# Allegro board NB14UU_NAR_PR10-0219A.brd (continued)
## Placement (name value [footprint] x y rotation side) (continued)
PR27  100K_0402_5%  [R_0402]  89.47 121.79 0 bottom
PR28  100K_0402_5%  [R_0402]  91.24 118.06 0 bottom
PR31  1M_0402_5%  [R_0402]  78.6 122.63 0 top
PR32  1M_0402_5%  [R_0402]  84.13 120.53 0 bottom
PR33  100K_0402_5%  [R_0402]  89.42 118.3 0 bottom
PR38  100_0402_5%  [R_0402]  144.89 41.6 0 top
PR39  100_0402_5%  [R_0402]  144.89 40.84 0 top
PR40  100_0402_5%  [R_0402]  144.89 40.08 0 top
PR41  0_0402_5%  [R0402_0OHM]  83.89 114.56 180 top
PR42  0_0402_5%  [R0402_0OHM]  83.82 115.5 90 top
PR43  0_0402_5%  [R_0402]  82.23 114.56 180 top
PR44  0_0402_5%  [R0402_0OHM]  83.82 118.07 270 top
PR45  10K_0402_5%  [R_0402]  80.58 114.56 180 top
PR46  0_0402_5%  [R0402_0OHM]  86.7 119.83 180 bottom
PR47  0_0402_5%  [R0402_0OHM]  78.67 117.05 270 top
PR49  0_0402_5%  [R0402_0OHM]  88.58 116.85 0 bottom
PR100  0_0603_5%  [R0603_0OHM]  204.72 31.19 270 bottom
PR102  499K_0402_1%  [R_0402]  202.57 38.17 180 bottom
PR103  499K_0402_1%  [R_0402]  202.57 37.35 180 bottom
PR104  0_0402_5%  [R0402_0OHM]  207.45 37.46 90 bottom
PR105  0_0402_5%  [R0402_0OHM]  206.69 37.46 90 bottom
PR106  4.7_1206_5%  [R_1206]  205.61 34.49 180 top
PR107  100K_0402_5%  [R_0402]  200.01 34.81 0 bottom
PR108  1K_0402_5%  [R_0402]  204.34 38.31 270 bottom
PR111  0_0603_5%  [R0603_0OHM]  82.29 73.73 0 bottom
PR112  4.7_1206_5%  [R_1206]  86.8 77.23 90 bottom
PR113  100K_0402_5%  [R_0402]  77.33 69.04 0 bottom
PR114  0_0402_5%  [R_0402]  74.48 69.34 90 bottom
PR116  1M_0402_1%  [R_0402]  75.37 70.64 270 bottom
PR117  1K_0402_5%  [R_0402]  74.48 71.5 90 bottom
PR119  0_0402_5%  [R0402_0OHM]  200.92 35.75 180 bottom
PR120  0_0402_5%  [R0402_0OHM]  200.92 36.51 180 bottom
PR202  4.7_1206_5%  [R_1206]  90.6 63 90 top
PR203  0_0603_5%  [R0603_0OHM]  87.37 63.32 180 bottom
PR204  102K_0402_1%  [R_0402]  87.61 68.72 0 bottom
PR205  0_0402_5%  [R_0402]  87.9 64.17 0 top
PR206  100K_0402_1%  [R_0402]  88.53 66.94 180 bottom
PR207  0_0402_5%  [R_0402]  88.48 65.54 180 top
PR208  0_0402_5%  [R0402_0OHM]  95.89 68.27 180 bottom
PR209  1M_0402_5%  [R_0402]  95.19 69.48 180 bottom
PR210  0_0402_5%  [R0402_0OHM]  96.91 70.43 180 top
PR212  1M_0402_5%  [R_0402]  95.26 70.43 180 top
PR302  1M_0402_1%  [R_0402]  235.28 131.23 0 top
PR303  4.7_1206_5%  [R_1206]  229.17 128.72 180 bottom
PR304  0_0603_5%  [R0603_0OHM]  231.26 127.84 270 top
PR306  22.1K_0402_1%  [R_0402]  231.83 134.64 270 top
PR307  0_0402_5%  [R_0402]  234.31 134.64 270 top
PR308  1K_0402_5%  [R_0402]  232.66 134.64 270 top
PR310  0_0402_5%  [R_0402]  235.14 133.73 90 top
PR311  29.4K_0402_1%  [R_0402]  233.48 133.73 90 top
PR312  22K_0402_1%  [R_0402]  236.19 132.03 180 top
PR313  100K_0402_5%  [R_0402]  236.29 130.34 0 top
PR314  0_0402_5%  [R0402_0OHM]  206.51 111.02 180 bottom
PR315  0_0402_5%  [R0402_0OHM]  204.16 129.49 180 bottom
PR402  0_0402_5%  [R0402_0OHM]  103.87 70.69 0 top
PR403  1M_0402_1%  [R_0402]  104.78 71.57 180 top
PR404  0_0402_5%  [R_0402]  105.6 70.74 90 top
PR405  4.7_0603_5%  [R_0603]  109.15 77.48 90 top
PR406  22K_0402_1%  [R_0402]  211.07 134.83 270 top
PR407  1M_0402_1%  [R_0402]  210.31 133.92 90 top
PR408  0_0402_5%  [R_0402]  213.16 127 90 top
PR409  4.7_0603_5%  [R_0603]  204.21 130.57 0 bottom
PR410  10K_0402_1%  [R_0402]  208.53 134.83 270 top
PR411  0_0402_5%  [R_0402]  210.88 127 90 top
PR412  0_0402_5%  [R_0402]  106.23 78.99 90 top
PR413  10K_0402_1%  [R_0402]  103.56 79.91 270 top
PR414  10K_0402_1%  [R_0402]  102.67 79.91 270 top
PR415  10K_0402_1%  [R_0402]  104.45 78.99 90 top
PR416  10K_0402_1%  [R_0402]  101.79 78.99 90 top
PR417  10K_0402_1%  [R_0402]  211.64 127 90 top
PR418  10K_0402_1%  [R_0402]  214.05 127.91 270 top
PR419  10K_0402_1%  [R_0402]  210.12 127.91 270 top
PR420  10K_0402_1%  [R_0402]  212.4 127.91 270 top
PR421  0_0402_5%  [R_0402]  108.01 79.91 270 top
PR422  0_0402_5%  [R_0402]  107.12 78.99 90 top
PR423  0_0402_5%  [R0402_0OHM]  206.89 127.96 180 top
PR424  100K_0402_1%  [R_0402]  208.02 127.98 270 top
PR425  0_0402_5%  [R_0402]  107.37 70.74 90 top
PR427  0_0402_5%  [R0402_0OHM]  105.34 78.99 90 top
PR428  1M_0402_1%  [R_0402]  209.35 127.91 270 top
PR429  0_0402_5%  [R0402_0OHM]  106.48 70.74 90 top
PR430  0_0402_5%  [R_0402]  207.77 134.83 270 top
PR501  20K_0402_1%  [R_0402]  203.13 109.15 90 bottom
PR502  4.7_0603_5%  [R_0603]  198.11 114.88 0 bottom
PR504  0_0402_5%  [R0402_0OHM]  200.59 113.37 270 top
PR505  1M_0402_1%  [R_0402]  200.59 111.66 270 top
PR506  10K_0402_1%  [R_0402]  204.78 110.07 270 bottom
PR509  1M_0402_1%  [R_0402]  280.92 98.87 90 top
PR510  10.2K_0402_1%  [R_0402]  286.63 98.3 90 top
PR511  100K_0402_5%  [R_0402]  279.14 99.78 270 top
PR512  5.1K_0402_1%  [R_0402]  287.52 96.45 90 top
PR513  0_0402_5%  [R0402_0OHM]  246.01 60.91 180 top
PR514  1M_0402_1%  [R_0402]  243.54 63.34 0 top
PR515  21.5K_0402_1%  [R_0402]  243.87 55.83 90 top
PR516  10K_0402_1%  [R_0402]  244.69 56.74 270 top
PR601  45.3_0402_1%  [R_0402]  88.67 101.45 90 bottom
PR602  0_0402_5%  [R0402_0OHM]  92.78 101.39 0 bottom
PR603  0_0402_5%  [R0402_0OHM]  91.97 102.33 90 bottom
PR604  75_0402_1%  [R_0402]  89.56 101.45 90 bottom
PR605  100_0402_1%  [R_0402]  90.44 101.45 90 bottom
PR606  0_0402_5%  [R0402_0OHM]  181.53 129.04 225 top
PR608  100K_0402_5%  [R_0402]  92.81 100.38 180 bottom
PR610  10K_0402_1%  [R_0402]  84.78 98.35 0 top
PR611  9.31K_0402_1%  [R_0402]  92.81 99.62 180 bottom
PR612  1.91K_0402_1%  [R_0402]  85.45 98.75 0 bottom
PR613  97.6K_0402_1%  [R_0402]  84.86 100.2 270 top
PR614  0_0402_5%  [R0402_0OHM]  85.45 99.64 0 bottom
PR615  0_0402_5%  [R_0402]  86.55 92.48 270 bottom
PR616  0_0402_5%  [R0402_0OHM]  85.45 100.53 0 bottom
PR617  4.3K_0402_1%  [R_0402]  87.51 97.61 180 bottom
PR618  49.9_0402_1%  [R_0402]  88.67 102.36 270 top
PR619  2.2_0603_5%  [R_0603]  180.27 132.53 90 top
PR620  0_0402_5%  [R0402_0OHM]  86.6 101.55 0 top
PR621  316_0402_1%  [R_0402]  82.95 98.8 270 top
PR622  2.49K_0402_1%  [R_0402]  82.88 97.08 0 top
PR623  2K_0402_1%  [R_0402]  83.84 98.8 270 top
PR624  3.65K_0603_1%  [R_0603]  172.4 131.58 270 bottom
PR625  0_0402_5%  [R0402_0OHM]  89.56 102.36 270 top
PR626  10_0402_1%  [R_0402]  90.44 102.36 270 top
PR627  4.7_1206_5%  [R_1206]  174.66 131.9 0 bottom
PR628  4.99K_0402_1%  [R_0402]  120.38 107.01 0 bottom
PR629  86.6K_0402_1%  [R_0402]  85.49 89 90 top
PR630  2.49K_0402_1%  [R_0402]  93.62 96.62 90 bottom
PR631  27.4K_0402_1%  [R_0402]  120.56 103.31 90 bottom
PR632  1K_0402_1%  [R_0402]  84.73 94.74 270 top
PR633  11K_0402_1%  [R_0402]  120.45 107.82 90 bottom
PR634  0_0402_5%  [R_0402]  85.66 92.48 270 bottom
PR635  10K_0402_1%  [R_0402]  87.27 90.78 90 top
PR636  634_0402_1%  [R_0402]  95.4 97.89 90 top
PR638  523_0402_1%  [R_0402]  84.78 95.55 0 top
PR639  3.09K_0402_1%  [R_0402]  89.26 93.16 0 bottom
PR640  374_0402_1%  [R_0402]  93.37 92.71 270 top
PR641  1K_0402_1%  [R_0402]  94.43 99.74 0 top
PR642  2.61K_0402_1%  [R_0402]  171.33 130.12 180 bottom
PR643  11K_0402_1%  [R_0402]  172.55 128.59 180 top
PR644  1K_0402_1%  [R_0402]  94.33 90.98 180 top
PR645  316_0402_1%  [R_0402]  89.05 90.78 90 top
PR646  316_0402_1%  [R_0402]  94.56 94.54 0 top
PR647  27.4K_0402_1%  [R_0402]  109.66 92.47 0 bottom
PR648  1.91K_0402_1%  [R_0402]  89.94 90.78 90 top
PR649  1.62K_0402_1%  [R_0402]  94.51 95.48 90 top
PR650  2K_0402_1%  [R_0402]  88.16 91.69 270 top
PR651  39.2K_0402_1%  [R_0402]  92.81 94.92 180 bottom
PR652  2K_0402_1%  [R_0402]  94.56 93.77 0 top
PR653  20M_0402_5%  [R_0402]  91.97 93.03 270 bottom
PR656  11K_0402_1%  [R_0402]  113.33 83.51 0 top
PR657  4.42K_0402_1%  [R_0402]  113.33 83.51 0 bottom
PR658  20M_0402_5%  [R_0402]  81.94 93.06 90 top
PR659  0_0402_5%  [R0402_0OHM]  118.68 96.83 90 bottom
PR660  3.9_0603_1%  [R_0603]  115.32 96.47 90 bottom
PR661  3.65K_0603_1%  [R_0603]  112.96 86.88 270 top
PR662  0_0402_5%  [R0402_0OHM]  101.64 85.54 0 bottom
PR663  4.7_1206_5%  [R_1206]  117.41 105.74 180 top
PR664  0_0402_5%  [R0402_0OHM]  101.64 84.72 0 bottom
PR665  3.9_0603_1%  [R_0603]  101.28 88.9 0 bottom
PR666  10_0402_1%  [R_0402]  120.38 109.55 0 bottom
PR667  3.65K_0603_1%  [R_0603]  118.49 109.17 180 top
PR668  100K_0402_1%  [R_0402]  116.21 109.17 180 top
PR669  4.7_1206_5%  [R_1206]  110.87 85.86 90 top
PR670  100K_0402_1%  [R_0402]  114.49 110.07 270 top
PR671  0_0402_5%  [R0402_0OHM]  104.71 101.78 90 bottom
PR672  3.9_0603_1%  [R_0603]  101.34 101.42 90 bottom
PR673  10_0402_1%  [R_0402]  105.47 113.24 270 top
PR674  3.65K_0603_1%  [R_0603]  102.99 113.17 90 top
PR675  100K_0402_1%  [R_0402]  104.01 114.58 270 top
PR676  4.7_1206_5%  [R_1206]  100.9 112.79 270 top
PR677  100K_0402_1%  [R_0402]  104.01 112.01 90 top
PR678  100_0402_1%  [R_0402]  86.6 102.69 0 top
PR679  0_0402_5%  [R0402_0OHM]  182.05 134.87 90 top
PR680  1_0603_5%  [R_0603]  101.38 87.82 270 bottom
PR687  0_0402_5%  [R0402_0OHM]  119.5 96.83 90 bottom
PR688  1_0603_5%  [R_0603]  116.4 96.56 0 bottom
PR691  1_0603_5%  [R_0603]  102.42 101.51 0 bottom
PR692  0_0402_5%  [R0402_0OHM]  105.52 101.78 90 bottom
PR693  11.8K_0402_1%  [R_0402]  86.6 100.66 0 top
PR700  0.01_1206_1%  [R_1206_4P-D]  91.69 36.76 90 bottom
PR701  1_0603_1%  [R_0603]  81.67 39.8 90 bottom
PR702  1_0603_1%  [R_0603]  82.94 39.8 90 bottom
PR703  0_0603_5%  [R_0603]  82.35 45.22 270 top
PR704  3.3_0603_1%  [R_0603]  84.78 40.56 90 bottom
PR705  442K_0402_1%  [R_0402]  82.57 46.09 180 top
PR706  100K_0402_5%  [R_0402]  81.66 47.74 0 top
PR707  4.7_0603_5%  [R_0603]  87.51 43.04 270 bottom
PR708  1_0805_5%  [R_0805]  78.08 45.92 0 top
PR709  0_0402_5%  [R0402_0OHM]  78.55 45.32 0 bottom
PR710  100K_0402_1%  [R_0402]  79.5 44.5 0 bottom
PR711  0.005_1206_1%  [R_1206_4P-D]  128.46 35.49 90 top
PR712  0_0402_5%  [R_0402]  80.22 45.25 90 bottom
PR713  0_0402_5%  [R0402_0OHM]  79.31 46.98 0 bottom
PR714  4.7_0603_5%  [R_0603]  89.93 45.58 180 bottom
PR715  0_0402_5%  [R0402_0OHM]  79.31 47.8 0 bottom
PR716  154K_0402_1%  [R_0402]  77.91 49.65 90 bottom
PR717  4.7_1206_5%  [R_1206]  106.57 39.97 90 bottom
PR718  4.7_1206_5%  [R_1206]  118.61 41.86 0 bottom
PR719  0_0402_5%  [R0402_0OHM]  79.44 48.56 0 bottom
PR720  1M_0402_1%  [R_0402]  76.06 50.87 0 bottom
PR721  0_0402_5%  [R0402_0OHM]  88.45 47.86 0 bottom
PR722  0_0402_5%  [R0402_0OHM]  79.41 49.35 0 bottom
PR723  100K_0402_1%  [R_0402]  80.78 50.84 90 bottom
PR724  100K_0402_1%  [R_0402]  79.96 51.75 270 bottom
PR725  105K_0402_1%  [R_0402]  83.77 50.84 90 top
PR726  100K_0402_1%  [R_0402]  83 51.75 270 top
PR727  0_0402_5%  [R0402_0OHM]  81.61 51.75 270 bottom
PR728  499_0402_1%  [R_0402]  83.33 50.85 180 bottom
PR729  0_0402_5%  [R0402_0OHM]  84.53 50.84 90 top
PR731  0_0402_5%  [R0402_0OHM]  86.23 50.84 90 top
PR733  1_0603_1%  [R_0603]  88.66 51.67 90 bottom
PR734  1_0603_1%  [R_0603]  87.01 51.67 90 bottom
PR735  0_0402_5%  [R_0402]  74.2 43.84 270 bottom
PR736  0_0402_5%  [R0402_0OHM]  73.31 42.92 90 bottom
PR737  0_0402_5%  [R0402_0OHM]  74.99 42.92 90 bottom
PR738  100_0402_5%  [R_0402]  85.98 51.66 90 bottom
PR739  100K_0402_1%  [R_0402]  75 46.49 270 bottom
PR740  0_0402_5%  [R0402_0OHM]  77.4 43.08 270 bottom
PR741  0_0402_5%  [R0402_0OHM]  77.91 48.28 270 bottom
PR743  0_0402_5%  [R0402_0OHM]  85.29 50.84 90 top
PR744  100K_0402_1%  [R_0402]  78.29 42.16 90 bottom
PR745  0_0402_5%  [R_0402]  82.24 51.75 270 top
PR746  0_0402_5%  [R_0402]  78.55 46.15 0 bottom
PR800  422K_0402_1%  [R_0402]  57.92 90.5 180 bottom
PR801  300K_0402_5%  [R_0402]  90.1 87.15 270 top
PR802  300K_0402_5%  [R_0402]  81.14 112.98 0 top
PR803  499K_0402_1%  [R_0402]  68.98 107.77 0 top
PR804  499K_0402_1%  [R_0402]  78.62 112.6 180 top
PR805  1.8M_0402_1%  [R_0402]  56.95 89.56 270 bottom
PR806  1K_0402_1%  [R_0402]  57.56 82.93 180 bottom
PR807  100K_0402_5%  [R_0402]  94.04 83.46 270 top
PR808  100K_0402_5%  [R_0402]  82.79 112.98 0 top
PR809  102K_0402_1%  [R_0402]  53.2 87.7 0 bottom
PR810  100K_0402_5%  [R_0402]  91.68 78.56 0 top
PR811  49.9K_0402_1%  [R_0402]  82.83 91.06 90 bottom
PR812  49.9K_0402_1%  [R_0402]  84.89 96.8 270 bottom
PR813  100K_0402_5%  [R_0402]  90.05 115.26 180 top
PR814  0_0402_5%  [R0402_0OHM]  89.15 116.99 270 top
PR815  37.4K_0402_1%  [R_0402]  54.11 85.04 180 bottom
PR816  0_0402_5%  [R0402_0OHM]  83.75 91.06 90 bottom
PR817  24.9K_0402_1%  [R_0402]  56.02 89.61 180 bottom
PR818  0_0402_5%  [R0402_0OHM]  81.47 95.15 270 bottom
PR819  100K_0402_5%  [R_0402]  84.64 91.06 90 bottom
PR820  0_0402_5%  [R0402_0OHM]  92.91 114.69 180 top
PR821  100K_0402_5%  [R_0402]  80.65 101.17 180 bottom
PR822  100K_0402_5%  [R_0402]  81.21 96.9 90 bottom
PR823  100K_0402_5%  [R_0402]  20.07 93.74 180 top
PR824  100K_0402_5%  [R_0402]  46.03 86.36 90 top
PR825  100K_0402_5%  [R_0402]  46.24 92.1 270 top
PR826  0_0402_5%  [R0402_0OHM]  47.05 92.1 270 top
PR827  0_0402_5%  [R0402_0OHM]  46.92 86.36 90 top
PR828  100K_0402_5%  [R_0402]  49.72 92.23 270 top
PR829  0_0402_5%  [R0402_0OHM]  51.11 88.64 90 top
PR830  100K_0402_5%  [R_0402]  40.06 88.14 90 top
PR831  499K_0402_1%  [R_0402]  62.37 86.69 180 bottom
PR832  102K_0402_1%  [R_0402]  58.73 88.64 90 bottom
PR833  100K_0402_5%  [R_0402]  41 87.2 0 top
PR834  0_0402_5%  [R0402_0OHM]  40.95 92.1 270 top
PR835  47K_0402_1%  [R_0402]  62.42 84.96 90 bottom
PR836  0_0402_5%  [R0402_0OHM]  66.99 90.55 90 bottom
PR838  100K_0402_5%  [R_0402]  41.77 91.26 0 top
PR839  100K_0402_5%  [R_0402]  43.92 87.2 0 top
PR840  0_0402_5%  [R0402_0OHM]  65.26 86.81 0 bottom
PR841  0_0402_5%  [R_0402]  40.06 90.83 270 top
PR842  97.6K_0402_1%  [R_0402]  62.42 87.5 90 bottom
PR843  37.4K_0402_1%  [R_0402]  59.67 89.48 0 bottom
PR844  0_0402_5%  [R0402_0OHM]  44.38 92.73 270 top
PR845  0_0402_5%  [R_0402]  43.49 92.73 270 top
PR846  10K_0402_5%  [R_0402]  66.18 90.62 180 bottom
PR851  100K_0402_5%  [R_0402]  94.24 78.56 180 top
PR852  100K_0402_5%  [R_0402]  88.32 115.19 90 top
PR853  0_0402_5%  [R0402_0OHM]  83.12 96.9 90 bottom
PR854  0_0402_5%  [R0402_0OHM]  82.23 96.9 90 bottom
PR855  10K_0402_5%  [R_0402]  82.74 102.11 90 bottom
PR856  0_0402_5%  [R_0402]  81.77 103.02 270 bottom
PR857  0_0402_5%  [R0402_0OHM]  84.01 96.9 90 bottom
PR858  0_0402_5%  [R0402_0OHM]  92.72 82.5 180 top
PR859  0_0402_5%  [R0402_0OHM]  84.51 103.02 270 bottom
PR860  0_0402_5%  [R_0402]  85.4 103.02 270 bottom
PR861  0_0402_5%  [R0402_0OHM]  90.94 78.56 180 top
PR862  100K_0402_5%  [R_0402]  72.96 104.8 270 top
PR865  100K_0402_5%  [R_0402]  88.4 114.41 180 top
PR866  0_0402_5%  [R0402_0OHM]  58.66 83.23 90 bottom
PR870  499K_0402_1%  [R_0402]  62.59 89.52 0 bottom
PR892  22_0805_5%  [R_0805]  65.4 113.41 90 top
PR893  22_0805_5%  [R_0805]  68.27 111.99 270 top
PR3001  0_0402_5%  [R_0402]  72.96 31.65 0 top
PR3002  200K_0402_1%  [R_0402]  72.97 32.54 0 top
PR3003  300K_0402_1%  [R_0402]  76.44 35.93 270 top
PR3004  200K_0402_1%  [R_0402]  74.81 37.25 180 top
PR3005  100K_0402_1%  [R_0402]  72.17 37.26 0 top
PR3006  0_0402_5%  [R_0402]  67.1 36.22 270 top
PR3007  237K_0402_1%  [R_0402]  67.1 34.53 0 top
PR3008  43.2K_0402_1%  [R_0402]  67.1 33.72 0 top
PR3009  14.7K_0402_1%  [R_0402]  70.59 38.54 90 top
PR3010  147K_0402_1%  [R_0402]  69.73 38.54 90 top
PR3011  43.2K_0402_1%  [R_0402]  69.73 37.59 0 top
PR3012  1K_0201_1%  [R_0201]  73.36 34.3 0 top
PR3013  1K_0201_1%  [R_0201]  70.11 33.99 270 top
PU2  RT9058-33GX_SOT89-3  [AP2204R-5P0TRG1_SOT89-3]  73.31 117.16 180 top
PU3  MC74VHC1G08DFT2G_SC70-5  [TC7SH08FU_SSOP5]  81.65 115.61 90 top
PU100  -  [SY8288BRAC_QFN20_3X3]  205.04 32.65 90 bottom
PU102  SYV828CRAC_QFN20_3X3  [SY8288CRAC_QFN20_3X3]  80.86 72.86 180 bottom
PU200  -  [SY8210AQVC_QFN19_4X3]  92.78 67.63 180 bottom
PU301  SY8286RAC_QFN20_3X3  [SY8288RAC_QFN20_3X3]  231.5 129.19 90 top
PU401  SY8057BQDC_QFN16_3X3  [SY8057QDC_QFN16_3X3]  107.27 74.63 180 top
PU402  SY8057CQDC_QFN16_3X3  [SY8057QDC_QFN16_3X3]  207.36 131.57 0 top
PU501  RT8097ALGE SOT23-6  [RT8097ALGE_SOT23-6]  201.28 111.49 90 bottom
PU502  S IC EM1109V-AD DFN3308 8P LDO  [AP7361C-FGE-7_U-DFN3030-8_3X3]  285.3 96.88 90 top
PU503  S IC EM1109V-AD DFN3308 8P LDO  [AP7361C-FGE-7_U-DFN3030-8_3X3]  242 58.06 0 top
PU602  ISL95857CHRTZ-T_TQFN40_5X5  [ISL62883CHRTZ-T_TQFN40_5X5-S]  87.25 98.52 270 top
PU610  FDMF3035 PQFN31 DR MOS D/CAFTER1835  [NCP302045MNTWG_PQFN33_5X5]  117.92 99.26 180 bottom
PU612  FDMF3035 PQFN31 DR MOS D/CAFTER1835  [NCP302045MNTWG_PQFN33_5X5]  104.07 86.3 90 bottom
PU613  FDMF3035 PQFN31 DR MOS D/CAFTER1835  [NCP302045MNTWG_PQFN33_5X5]  103.94 104.21 180 bottom
PU614  ISL95808HRZ-TS2778_DFN8_2X2~D  [ISL95808HRZ-TS2378_DFN8_2X2-S]  181.64 131.16 0 top
PU700  ISL9538HRTZ-TS2778 TQFN 32P CHARGER  [ISL88738HRTZ-T_TQFN32_4X4]  86.39 47.87 180 bottom
PU701  MC74VHC1G08DFT2G_SC70-5  [TC7SH08FU_SSOP5]  75.99 46.11 0 bottom
PU800  AS393MMTR-G1 MSOP 8P OP  [LM393DGKR_VSSOP8]  55.67 85.33 0 bottom
PU801  MC74VHC1G08DFT2G_SC70-5  [TC7SH08FU_SSOP5]  83.51 98.95 180 bottom
PU3000  -  [AZV3002RL-7_U-FLGA8_1P65X1P65]  72.28 34.35 90 top
QC2  L2N7002DW1T1G_SC88-6  [DMN65D8LDW-7_SOT363-6]  200.04 99.6 0 top
QC4  L2N7002DW1T1G_SC88-6  [DMN65D8LDW-7_SOT363-6]  188.03 116.6 180 bottom
QC6  -  [L2N7002WT1G_SC-70-3]  191.01 68.78 90 top
QC7  -  [LP2301ALT1G_SOT23-3]  188.31 69.66 0 top
QC8  S TR BSS138W 1N SOT-323-3  [L2N7002WT1G_SC-70-3]  264.47 82.68 0 top
QE2  L2N7002DW1T1G_SC88-6  [DMN65D8LDW-7_SOT363-6]  253.06 75.95 180 top
QE3  LMBT3904WT1G NPN SC70-3  [MMST3904-7-F_SOT323-3]  151.76 95.2 90 top
QE4  LMBT3904WT1G NPN SC70-3  [MMST3904-7-F_SOT323-3]  251.65 82.81 180 top
QE5  LMBT3904WT1G NPN SC70-3  [MMST3904-7-F_SOT323-3]  266.31 31.89 270 bottom
QE6  LMBT3904WT1G NPN SC70-3  [MMST3904-7-F_SOT323-3]  121.1 97.9 180 bottom
QE7  LMBT3904WT1G NPN SC70-3  [MMST3904-7-F_SOT323-3]  176.34 39.44 90 bottom
QE11  -  [L2N7002WT1G_SC-70-3]  250.31 78.94 90 top
QE12  -  [L2N7002WT1G_SC-70-3]  248.98 109.74 0 top
QE15  -  [LP2301ALT1G_SOT23-3]  245.7 119.45 90 top
QE17  -  [L2N7002WT1G_SC-70-3]  246.25 122.76 270 top
QE20  -  [L2N7002WT1G_SC-70-3]  258.18 113.93 270 top
QE21  L2N7002DW1T1G_SC88-6  [DMN65D8LDW-7_SOT363-6]  252.61 112.97 270 top
QL1  L2N7002DW1T1G_SC88-6  [DMN65D8LDW-7_SOT363-6]  287.44 112.47 0 top
QN1  L2N7002DW1T1G_SC88-6  [DMN65D8LDW-7_SOT363-6]  252.87 35.5 180 top
QN6  -  [L2N7002WT1G_SC-70-3]  260.85 53.41 90 bottom
QR1  -  [L2N7002WT1G_SC-70-3]  295.78 28.01 270 top
QT1  -  [DMN66D0LDW-7_SOT363-6]  60.24 94.88 0 top
QT10  L2N7002DW1T1G_SC88-6  [DMN65D8LDW-7_SOT363-6]  53.84 110.82 270 top
QV1  -  [AO6405_TSOP6]  133.09 135.87 180 top
QV2  -  [L2N7002WT1G_SC-70-3]  124.67 135.34 0 top
QV7  -  [L2N7002WT1G_SC-70-3]  114.87 135.77 0 top
QV8  -  [LP2301ALT1G_SOT23-3]  122.16 134.07 90 top
QV18  -  [MMBT3906H_SOT23-3]  99.78 132.41 90 top
QV19  LMBT3904WT1G NPN SC70-3  [MMBT3904WT1G_SC70-3]  97.09 127.77 0 top
QV20  -  [MMBT3906H_SOT23-3]  145.37 126.06 90 top
QV21  LMBT3904WT1G NPN SC70-3  [MMBT3904WT1G_SC70-3]  137.9 121.91 0 top
QZ1  -  [LP2301ALT1G_SOT23-3]  127.95 123.51 270 top
QZ3  -  [LMUN5111T1G_SC70-3]  246.87 110.18 270 top
QZ7  L2N7002DW1T1G_SC88-6  [DMN65D8LDW-7_SOT363-6]  274.7 117.6 270 top
QZ15  -  [BSS138W-7-F_SOT323-3]  269.3 72.4 180 top
QZ17  -  [PJE138K_SOT523-3]  265.88 42.1 270 bottom
QZ18  -  [LP2301ALT1G_SOT23-3]  274.61 120.57 270 top
QZ19  -  [L2N7002WT1G_SC-70-3]  283.44 74.56 180 top
QZ21  -  [LMBT3904WT1G_SC70-3]  242.39 111.34 90 top
QZ22  -  [BSS138W-7-F_SOT323-3]  260.03 44.2 0 top
RA3  0_0603_5%  [R0603_0OHM]  279.14 60.21 180 top
RA5  2.2K_0402_5%  [R_0402]  296.27 34.49 0 bottom
RA6  2.2K_0402_5%  [R_0402]  296.38 35.87 90 bottom
RA7  16.2_0402_1%  [R_0402]  292.59 56.21 0 top
RA8  16.2_0402_1%  [R_0402]  292.59 54.94 0 top
RA9  33_0402_5%  [R_0402]  286.95 47.5 90 top
RA12  1K_0402_5%  [R_0402]  290.81 46.68 0 top
RA13  1K_0402_5%  [R_0402]  290.76 45.93 270 top
RA14  22_0402_5%  [R_0402]  283.84 47.5 90 top
RA17  33_0402_5%  [R_0402]  284.79 48.41 270 top
RA18  10K_0402_5%  [R_0402]  280.08 45.92 0 top
RA35  0_0402_5%  [R0402_0OHM]  292.74 45.03 180 top
RA36  0_0402_5%  [R0402_0OHM]  278.9 57.86 180 top
RA37  0_0402_5%  [R0402_0OHM]  285.24 61.53 90 top
RA44  100K_0402_5%  [R_0402]  289.17 58.04 90 top
RA45  10K_0402_5%  [R_0402]  289.05 45.93 270 top
RA48  0_0402_5%  [R0402_0OHM]  278.43 45.92 0 top
RA50  0_0402_5%  [R_0402]  281.95 44.9 180 top
RA51  10K_0402_5%  [R_0402]  290.81 47.44 0 top
RA52  100K_0402_5%  [R_0402]  283.01 45.72 90 top
RA53  0_0402_5%  [R0402_0OHM]  294.88 53.22 0 top
RA54  0_0402_5%  [R_0402]  294.88 54.05 0 top
RA57  4.7K_0402_5%  [R_0402]  292.59 56.97 0 top
RA58  4.7K_0402_5%  [R_0402]  294.32 55.84 270 top
RA59  100K_0402_1%  [R_0402]  295.79 51.51 180 top
RA60  200K_0402_1%  [R_0402]  290.95 51.52 270 top
RC2  100K_0402_5%  [R_0402]  193.18 104.09 180 top
RC5  121_0402_1%  [R_0402]  169.22 93.63 90 top
RC6  100K_0402_5%  [R_0402]  190.25 107.52 180 bottom
RC7  100_0402_1%  [R_0402]  169.22 92.9 270 top
RC8  24.9_0402_1%  [R_0402]  153.92 116.29 270 top
RC10  200_0402_1%  [R_0402]  185.94 101.67 180 bottom
RC11  1K_0402_1%  [R_0402]  183.86 81.72 90 bottom
RC12  1K_0402_5%  [R_0402]  198.79 100.73 90 top
RC14  1K_0402_5%  [R_0402]  198.79 99.86 270 top
RC15  1K_0402_5%  [R_0402]  188.58 98.75 0 bottom
RC19  33_0402_5%  [R_0402]  183.17 79.5 270 top
RC20  499_0402_1%  [R_0402]  194.96 102.26 0 top
RC24  0_0201_5%  [R_0201]  208.81 86.81 0 bottom
RC25  4.99_0201_1%  [R_0201]  207.54 86.81 0 bottom
RC26  4.99_0201_1%  [R_0201]  206.27 86.81 0 bottom
RC27  4.99_0201_1%  [R_0201]  205 86.81 0 bottom
RC28  0_0201_5%  [R0201_0OHM]  203.73 86.81 0 bottom
RC29  4.99_0201_1%  [R_0201]  202.46 86.81 0 bottom
RC30  4.99_0201_1%  [R_0201]  201.19 86.81 0 bottom
RC31  0_0402_5%  [R_0402]  205.56 83.96 180 top
RC32  0_0201_5%  [R0201_0OHM]  218.47 93.29 180 bottom
RC33  49.9_0201_1%  [R_0201]  218.35 90.75 180 bottom
RC35  33_0201_1%  [R_0201]  217.9 100.4 180 bottom
RC46  2.2K_0402_5%  [R_0402]  191.83 78.55 90 top
RC47  113_0402_1%  [R_0402]  176.88 115.97 90 top
RC48  1K_0402_5%  [R_0402]  180.52 74.32 270 top
RC49  1K_0402_5%  [R_0402]  176.12 115.97 90 top
RC50  100_0402_1%  [R_0402]  178.35 115.98 0 top
RC51  10K_0402_5%  [R_0402]  201.99 79.4 270 top
RC53  10K_0402_5%  [R_0402]  193.35 79.46 270 top
RC56  20K_0402_5%  [R_0402]  173.26 74.84 270 top
RC57  20K_0402_5%  [R_0402]  205.04 75.72 270 top
RC58  10K_0402_5%  [R_0402]  196.78 79.42 270 top
RC59  200K_0402_1%  [R_0402]  183.37 114.37 0 bottom
RC60  0_0402_5%  [R_0402]  220.88 76.81 180 top
RC61  100K_0402_5%  [R_0402]  182.21 81.72 90 bottom
RC62  100K_0402_5%  [R_0402]  184.65 81.72 90 bottom
RC63  10K_0402_5%  [R_0402]  188.58 102.82 0 bottom
RC65  100K_0402_5%  [R_0402]  218.44 80.17 0 top
RC66  10M_0402_5%  [R_0402]  173.13 78.4 270 top
RC67  1K_0402_5%  [R_0402]  182.28 75.92 270 top
RC68  10K_0402_5%  [R_0402]  186.47 75.92 270 top
RC69  1M_0402_5%  [R_0402]  172.43 74.84 270 top
RC71  1K_0402_5%  [R_0402]  168.97 118.68 90 bottom
RC72  10K_0402_5%  [R_0402]  183.1 75.92 270 top
RC73  10K_0402_5%  [R_0402]  177.2 82.78 270 bottom
RC75  10K_0402_5%  [R_0402]  171.16 82.78 270 bottom
RC77  1K_0402_5%  [R_0402]  158.68 113.56 270 bottom
RC78  62_0402_5%  [R_0402]  168.08 119.59 270 bottom
RC82  10K_0201_5%  [R_0201]  188.69 115.64 180 bottom
RC84  499_0402_1%  [R_0402]  146.91 116.44 270 bottom
RC86  51_0402_5%  [R_0402]  130.06 116.41 180 top
RC87  1K_0201_5%  [R_0201]  138.23 116.96 90 top
RC92  33_0402_5%  [R_0402]  171.42 73.87 90 top
RC93  33_0402_5%  [R_0402]  170.59 73.87 90 top
RC94  100K_0402_5%  [R_0402]  181.32 81.87 90 bottom
RC95  100K_0402_5%  [R_0402]  178.85 79.52 90 bottom
RC96  100K_0402_5%  [R_0402]  186.16 82.56 0 bottom
RC101  20K_0402_5%  [R_0402]  191.27 92.91 180 bottom
RC104  10K_0402_5%  [R_0402]  189.29 116.46 90 bottom
RC106  49.9_0402_1%  [R_0402]  172 94.29 0 top
RC107  49.9_0402_1%  [R_0402]  174.33 94.45 0 top
RC108  49.9_0402_1%  [R_0402]  144.65 115.38 90 top
RC109  49.9_0402_1%  [R_0402]  145.54 115.38 90 top
RC116  200_0402_1%  [R_0402]  192.54 91.01 180 bottom
RC120  1K_0402_1%  [R_0402]  78.42 136.55 270 top
RC121  0_0402_5%  [R0402_0OHM]  75.19 135.71 180 top
RC122  0_0402_5%  [R_0402]  75.19 136.47 180 top
RC123  1K_0402_5%  [R_0402]  86.04 133.35 90 top
RC124  1K_0402_5%  [R_0402]  85.28 133.35 90 top
RC125  1.5K_0402_5%  [R_0402]  88.56 128.65 90 bottom
RC126  1K_0402_5%  [R_0402]  78.42 134.26 270 top
RC128  0_0402_5%  [R0402_0OHM]  90.48 133.35 90 top
RC129  0_0402_5%  [R_0402]  192.26 103.78 0 bottom
RC130  51_0402_5%  [R_0402]  130.06 117.17 180 top
RC131  51_0402_5%  [R_0402]  128.33 118.01 270 top
RC132  150_0402_5%  [R_0402]  77.66 133.35 90 top
RC133  1.5K_0402_5%  [R_0402]  91.24 133.35 90 top
RC134  51_0402_5%  [R_0402]  133.92 118.9 270 top
RC135  100_0402_5%  [R_0402]  132.52 118.9 270 top
RC136  51_0402_5%  [R_0402]  140.09 117.04 180 top
RC137  3K_0402_5%  [R_0402]  89.73 128.2 90 bottom
RC138  51_0402_5%  [R_0402]  74.61 134.26 270 top
RC139  51_0402_5%  [R_0402]  136.46 116.96 90 top
RC150  100_0402_1%  [R_0402]  157.03 115.38 90 top
RC151  100_0402_1%  [R_0402]  154.74 116.29 270 top
RC153  0_0603_5%  [R0603_0OHM]  164.21 114.12 270 bottom
RC154  56_0402_1%  [R_0402]  148.38 118.6 270 bottom
RC155  220_0402_5%  [R_0402]  148.56 115.52 90 bottom
RC156  100_0402_1%  [R_0402]  147.56 118.6 270 bottom
RC157  0_0402_5%  [R0402_0OHM]  147.73 115.52 90 bottom
RC158  43_0402_5%  [R_0402]  149.21 118.6 270 bottom
RC159  0_0402_5%  [R0402_0OHM]  149.38 115.52 90 bottom
RC160  100_0402_1%  [R_0402]  138.74 113.66 90 bottom
RC161  100_0402_1%  [R_0402]  136.46 114.58 270 bottom
RC163  100_0402_1%  [R_0402]  108.02 81.29 180 top
RC164  100_0402_1%  [R_0402]  164.27 116.36 270 top
RC165  0_0201_5%  [R0201_0OHM]  106.21 81.29 180 top
RC166  100_0402_1%  [R_0402]  166.55 115.44 90 top
RC173  0.01_0603_1%  [R_0603]  175.56 124.06 180 top
RC175  0.01_0603_1%  [R_0603]  196.46 116.15 180 bottom
RC176  2.2K_0402_5%  [R_0402]  178.62 113.54 90 bottom
RC178  2.2K_0402_5%  [R_0402]  197.49 105.86 180 bottom
RC183  2.2K_0402_5%  [R_0402]  178.85 82.78 270 bottom
RC187  4.7K_0402_5%  [R_0402]  169.7 73.87 90 top
RC189  10K_0402_5%  [R_0402]  194.29 91.89 0 top
RC214  0_0402_5%  [R_0402]  184.77 70.69 0 top
RC215  0_0402_5%  [R0402_0OHM]  194.6 75.01 90 top
RC216  0_0603_5%  [R0603_0OHM]  86.99 131.07 0 top
RC217  0_0402_5%  [R_0402]  76.89 134.26 270 top
RC218  1K_0402_1%  [R_0402]  169.73 119.59 270 bottom
RC219  49.9_0402_1%  [R_0402]  150.03 118.6 270 bottom
RC220  100K_0402_1%  [R_0402]  193.71 75.92 270 top
RC221  0_0402_5%  [R0402_0OHM]  243.31 116.66 0 bottom
RC222  1K_0402_5%  [R_0402]  244.23 118.69 180 bottom
RC229  100K_0402_5%  [R_0402]  197.64 75.92 270 top
RC230  100K_0402_5%  [R_0402]  195.68 75.89 270 top
RC231  100K_0402_5%  [R_0402]  170.51 79.83 180 top
RC232  100K_0402_5%  [R_0402]  189.14 75.92 270 top
RC233  100K_0402_5%  [R_0402]  187.36 75.92 270 top
RC234  100K_0402_5%  [R_0402]  191.8 75.92 270 top
RC235  150_0402_5%  [R_0402]  75.37 134.26 270 top
RC236  10K_0402_5%  [R_0402]  76.13 134.26 270 top
RC237  100K_0402_5%  [R_0402]  221.42 79.31 90 top
RC239  0_0402_5%  [R0402_0OHM]  82.35 133.35 90 top
RC240  0_0402_5%  [R0402_0OHM]  83.12 133.35 90 top
RC241  1.5K_0402_5%  [R_0402]  88.7 134.26 270 top
RC243  0_0402_5%  [R0402_0OHM]  193.17 102.82 180 bottom
RC244  10K_0402_1%  [R_0402]  184.88 78.59 90 top
RC248  2.2K_0402_5%  [R_0402]  193.91 102.82 0 bottom
RC266  4.7K_0402_5%  [R_0402]  188.58 97.99 0 bottom
RC277  4.7K_0402_5%  [R_0402]  192.17 99.98 0 top
RC278  10K_0402_5%  [R_0402]  199.26 79.42 270 top
RC279  10K_0402_5%  [R_0402]  197.61 79.42 270 top
RC288  10K_0402_5%  [R_0402]  190.35 92.15 0 bottom
RC289  33_0402_5%  [R_0402]  205.11 100.4 180 bottom
RC292  10K_0402_5%  [R_0402]  198.43 79.42 270 top
RC297  0_0201_5%  [R0201_0OHM]  194.92 91.13 180 top
RC298  0_0402_5%  [R_0402]  160.46 112.65 90 bottom
RC299  33_0402_5%  [R_0402]  204.73 90.65 180 bottom
RC302  0_0201_5%  [R_0201]  217.9 102.94 180 bottom
RC317  150K_0402_5%  [R_0402]  178.02 82.78 270 bottom
RC318  2.2K_0402_5%  [R_0402]  202.47 100.79 90 top
RC319  2.2K_0402_5%  [R_0402]  202.47 99.99 270 top
RC323  10K_0402_5%  [R_0402]  181.72 71.7 0 top
RC328  0_0402_5%  [R0402_0OHM]  136.44 116.15 0 top
RC337  0_0402_5%  [R0402_0OHM]  205.37 106.63 180 bottom
RC344  10K_0402_5%  [R_0402]  185.64 75.92 270 top
RC345  100K_0402_5%  [R_0402]  198.89 94.69 180 top
RC347  499_0402_1%  [R_0402]  194.96 103.91 0 top
RC348  499_0402_1%  [R_0402]  194.96 101.44 0 top
RC362  1K_0402_5%  [R_0402]  190.67 94.75 0 top
RC363  1K_0402_5%  [R_0402]  190.67 95.51 0 top
RC366  15_0402_5%  [R_0402]  187.29 79.48 270 top
RC367  15_0402_5%  [R_0402]  186.53 79.5 270 top
RC368  15_0402_5%  [R_0402]  188.06 79.48 270 top
RC369  15_0402_5%  [R_0402]  185.71 79.5 270 top
RC397  20K_0402_5%  [R_0402]  192.17 100.8 0 top
RC400  10K_0402_5%  [R_0402]  188.58 97.23 0 bottom
RC401  10K_0402_5%  [R_0402]  185.94 97.99 180 bottom
RC402  60.4_0402_1%  [R_0402]  180.14 113.54 90 bottom
RC403  0_0402_5%  [R0402_0OHM]  172.31 78.4 270 top
RC404  0_0402_5%  [R0402_0OHM]  172.31 80.43 270 top
RC405  1K_0402_1%  [R_0402]  79.18 136.55 270 top
RC406  1K_0402_1%  [R_0402]  79.94 136.55 270 top
RC407  1K_0402_1%  [R_0402]  80.7 136.55 270 top
RC409  1K_0402_1%  [R_0402]  84.26 136.55 270 top
RC410  1K_0402_1%  [R_0402]  85.02 136.55 270 top
RC411  1K_0402_1%  [R_0402]  87.26 135.6 180 top
RC412  1K_0402_1%  [R_0402]  78.93 131.85 270 top
RC413  1K_0402_1%  [R_0402]  79.69 131.85 270 top
RC414  1K_0402_1%  [R_0402]  80.45 131.85 270 top
RC415  1K_0402_1%  [R_0402]  81.21 131.85 270 top
RC416  1K_0402_1%  [R_0402]  84.26 128.65 90 bottom
RC417  1K_0402_1%  [R_0402]  85.15 128.65 90 bottom
RC418  1K_0402_1%  [R_0402]  86.04 128.65 90 bottom
RC419  1K_0402_1%  [R_0402]  143.86 116.29 270 top
RC420  0_0201_5%  [R_0201]  131.31 90.92 270 bottom
RC422  0.01_0603_1%  [R_0603]  174.48 120.94 180 top
RC425  0_0402_5%  [R0402_0OHM]  165.03 115.44 90 top
RC426  0_0402_5%  [R0402_0OHM]  165.79 115.44 90 top
RC429  0_0402_5%  [R0402_0OHM]  155.51 115.38 90 top
RC430  0_0402_5%  [R0402_0OHM]  156.27 115.38 90 top
RC431  100K_0402_5%  [R_0402]  192.58 72.29 180 top
RC432  499K_0402_1%  [R_0402]  190.79 72.3 270 top
RC433  49.9K_0402_1%  [R_0402]  190.74 70.56 0 top
RC436  100_0402_1%  [R_0402]  113.66 93.24 270 top
RC437  2.2K_0402_5%  [R_0402]  197.49 104.34 180 bottom
RC438  2.2K_0402_5%  [R_0402]  197.49 105.1 180 bottom
RC439  0_0402_5%  [R_0402]  184.77 69.8 0 top
RC440  0_0402_5%  [R0402_0OHM]  185.9 71.77 90 top
RC441  0_0402_5%  [R_0402]  198.46 75.91 0 top
RC442  0_0402_5%  [R0402_0OHM]  198.46 75.08 0 top
RC443  4.7K_0402_5%  [R_0402]  193.68 94.43 180 bottom
RC444  20K_0402_5%  [R_0402]  192.77 93.67 0 bottom
RC445  0_0402_5%  [R0402_0OHM]  204.2 75.72 180 top
RC446  20K_0402_5%  [R_0402]  191.27 93.67 180 bottom
RC448  150_0402_1%  [R_0402]  190.13 90.43 180 bottom
RC451  20K_0402_5%  [R_0402]  179.13 77.49 270 top
RC452  4.7K_0402_5%  [R_0402]  178.37 76.58 90 top
RC454  20K_0402_5%  [R_0402]  179.68 80.43 270 bottom
RC502  2.2K_0402_5%  [R_0402]  179.38 113.54 90 bottom
RC503  2.2K_0402_5%  [R_0402]  197.49 106.63 180 bottom
RC504  80.6_0402_1%  [R_0402]  169.93 95.3 180 top
RC505  1K_0402_1%  [R_0402]  180.5 81.87 90 bottom
RC506  499_0402_1%  [R_0402]  194.96 103.09 0 top
RC507  1K_0402_5%  [R_0402]  188.58 100.53 0 bottom
RC515  4.7K_0402_5%  [R_0402]  185.42 82.64 270 bottom
RC518  4.7K_0402_5%  [R_0402]  179.67 82.78 270 bottom
RC519  4.7K_0402_5%  [R_0402]  183.04 82.64 270 bottom
RC520  1K_0402_5%  [R_0402]  193.17 106.45 180 bottom
RC521  1K_0402_5%  [R_0402]  193.17 105.69 180 bottom
RC522  10K_0402_5%  [R_0402]  203.77 79.4 270 top
RC523  10K_0402_5%  [R_0402]  202.88 79.4 270 top
RC525  10K_0402_5%  [R_0402]  200.21 79.4 270 top
RC526  0_0402_5%  [R0402_0OHM]  203.77 81.68 270 top
RC527  0_0402_5%  [R0402_0OHM]  202.88 81.68 270 top
RC528  0_0402_5%  [R0402_0OHM]  201.99 81.68 270 top
RC530  0_0402_5%  [R_0402]  161.22 112.65 90 bottom
RC531  0_0402_5%  [R0402_0OHM]  182.51 114.37 180 bottom
RC532  0_0402_5%  [R0402_0OHM]  173.13 79.52 90 top
RC536  10K_0402_5%  [R_0402]  177.6 77.49 270 top
RC537  4.7K_0402_5%  [R_0402]  190.35 94.43 0 bottom
RC555  10K_0402_5%  [R_0402]  172.97 81.62 270 bottom
RC558  1K_0402_1%  [R_0402]  146.73 118.6 270 bottom
RC559  0_0402_5%  [R0402_0OHM]  170.49 119.59 270 bottom
RC560  33_0402_5%  [R_0402]  166.91 72.09 90 top
RC561  33_0402_5%  [R_0402]  168.88 72.09 90 top
RC562  1K_0402_5%  [R_0402]  169.7 72.09 90 top
RC564  0_0402_5%  [R_0402]  114.42 93.24 270 top
RC565  0_0402_5%  [R_0402]  139.63 113.66 90 bottom
RC566  0_0402_5%  [R0402_0OHM]  187.33 115.64 180 bottom
RC567  10K_0402_5%  [R_0402]  195.13 79.45 270 top
RC568  100_0402_5%  [R_0402]  131.68 117.17 0 top
RC569  51_0402_5%  [R_0402]  134.75 117.17 180 top
RC570  49.9_0201_1%  [R_0201]  212.02 95.87 270 bottom
RC571  49.9_0201_1%  [R_0201]  211.13 95.87 270 bottom
RC572  49.9_0201_1%  [R_0201]  210.24 95.87 270 bottom
RC573  33_0201_1%  [R_0201]  212.91 97.06 90 bottom
RC574  33_0201_1%  [R_0201]  212.02 97.06 90 bottom
RC575  33_0201_1%  [R_0201]  211.13 97.06 90 bottom
RC576  33_0201_1%  [R_0201]  210.24 97.06 90 bottom
RC624  49.9_0402_1%  [R_0402]  151.63 115.38 90 top
RC631  0_0402_5%  [R0402_0OHM]  137.22 113.66 90 bottom
RC632  0_0402_5%  [R0402_0OHM]  137.98 113.66 90 bottom
RC640  75K_0402_5%  [R_0402]  191.59 93.23 180 top
RC660  0_0201_5%  [R_0201]  200.59 92 270 top
RC710  33_0402_5%  [R_0402]  198.91 96.24 180 top
RC711  33_0402_5%  [R_0402]  198.89 95.46 180 top
RC723  1K_0402_5%  [R_0402]  83.5 136.55 270 top
RC724  20K_0402_5%  [R_0402]  262.31 42.44 270 top
RC725  10K_0402_5%  [R_0402]  188.82 79.48 270 top
RC726  10K_0402_5%  [R_0402]  196.58 103.58 0 bottom
RC727  0_0402_5%  [R0402_0OHM]  200.21 81.68 270 top
RC728  33_0402_5%  [R_0402]  183.37 113.61 0 bottom
RC729  33_0402_5%  [R_0402]  181.59 113.61 0 bottom
RC730  1K_0402_5%  [R_0402]  193.17 104.7 180 bottom
RC731  100K_0402_5%  [R_0402]  148.64 116.22 0 top
RC732  100K_0402_5%  [R_0402]  148.64 115.45 0 top
RC733  20K_0402_5%  [R_0402]  263.58 42.44 270 top
RC734  49.9_0201_1%  [R_0201]  212.91 95.87 270 bottom
RC735  0_0402_5%  [R0402_0OHM]  129.14 117.93 0 top
RC736  0_0402_5%  [R0402_0OHM]  134.68 118.9 270 top
RC737  0_0402_5%  [R0402_0OHM]  131.76 118.9 270 top
RC738  0_0402_5%  [R0402_0OHM]  218.25 76.81 0 top
RC739  0_0402_5%  [R0402_0OHM]  221.36 78.52 0 top
RC743  10K_0402_5%  [R_0402]  188.58 103.58 0 bottom
RC744  10K_0402_5%  [R_0402]  188.58 101.29 0 bottom
RC745  10K_0402_5%  [R_0402]  188.58 102.05 0 bottom
RC747  100K_0402_5%  [R_0402]  195.96 79.42 270 top
RC748  10K_0402_5%  [R_0402]  194.96 100.61 0 top
RC749  100K_0402_5%  [R_0402]  194.96 98.96 0 top
RC751  10K_0402_5%  [R_0402]  185.48 116.36 270 bottom
RC752  71.5K_0402_1%  [R_0402]  190.67 93.99 0 top
RC756  10K_0402_5%  [R_0402]  189.91 96.34 0 top
RC757  20K_0402_5%  [R_0402]  202.17 105.74 0 bottom
RC758  20K_0402_5%  [R_0402]  202.17 103.96 0 bottom
RC759  20K_0402_5%  [R_0402]  202.17 104.85 0 bottom
RC760  20K_0402_5%  [R_0402]  202.17 103.07 0 bottom
RC761  100K_0402_5%  [R_0402]  184.82 75.92 270 top
RC763  100K_0402_5%  [R_0402]  200.59 92.71 90 top
RC764  10K_0402_5%  [R_0402]  194.83 104.85 180 bottom
RC765  10K_0402_5%  [R_0402]  194.83 106.63 180 bottom
RC766  10K_0402_5%  [R_0402]  194.83 105.86 180 bottom
RC829  1K_0402_5%  [R_0402]  191.27 96.47 180 bottom
RC830  1K_0402_5%  [R_0402]  190.35 95.2 0 bottom
RC831  4.7K_0402_5%  [R_0402]  192.59 78.55 90 top
RC832  4.7K_0402_5%  [R_0402]  198.92 97.03 180 top
RC833  100K_0402_5%  [R_0402]  194.11 79.46 270 top
RC834  100K_0402_5%  [R_0402]  179.89 77.49 270 top
RC836  10K_0402_5%  [R_0402]  199.75 105.74 0 bottom
RC837  10K_0402_5%  [R_0402]  199.75 103.96 0 bottom
RC838  10K_0402_5%  [R_0402]  199.75 103.07 0 bottom
RC839  10K_0402_5%  [R_0402]  199.75 104.85 0 bottom
RC840  10K_0402_5%  [R_0402]  189.91 97.1 0 top
RC841  10K_0402_5%  [R_0402]  190.98 79.42 270 top
RC842  20K_0402_5%  [R_0402]  198.92 97.79 180 top
RC843  10K_0402_5%  [R_0402]  200.67 106.63 180 bottom
RC844  10K_0402_5%  [R_0402]  203.08 106.63 180 bottom
RC845  0_0402_5%  [R0402_0OHM]  194.7 96.09 180 top
RC847  100K_0402_5%  [R_0402]  188.58 96.47 0 bottom
RC848  0_0201_5%  [R0201_0OHM]  169.63 82.62 0 top
RC849  8.2K_0402_5%  [R_0402]  190.15 79.42 270 top
RC850  0_0201_5%  [R0201_0OHM]  132.43 119.58 180 top
RC851  0_0201_5%  [R0201_0OHM]  134.13 119.58 0 top
RC852  0_0201_5%  [R0201_0OHM]  128.42 118.69 0 top
RC853  0_0201_5%  [R0201_0OHM]  92.39 128.5 90 bottom
RC862  10K_0402_5%  [R_0402]  197.97 93.87 0 top
RC864  0_0603_5%  [R0603_0OHM]  167.41 118.3 90 top
RC865  10K_0402_5%  [R_0402]  199.75 107.52 0 bottom
RC866  10K_0402_5%  [R_0402]  241.18 126.64 180 top
RC867  0_0201_5%  [R_0201]  196.78 92.66 270 top
RC868  75K_0402_5%  [R_0402]  197.9 82.71 0 top
RD4  0_0402_5%  [R_0402]  166.68 43.43 90 bottom
RD5  0_0402_5%  [R0402_0OHM]  165.92 44.35 270 bottom
RD6  0_0402_5%  [R_0402]  167.44 43.43 90 bottom
RD7  0_0402_5%  [R0402_0OHM]  168.21 44.35 270 bottom
RD8  0_0402_5%  [R_0402]  145.63 46.45 90 top
RD9  0_0402_5%  [R0402_0OHM]  144.8 47.36 270 top
RD10  0_0603_5%  [R0603_0OHM]  166.24 52.46 90 top
RD11  470_0402_1%  [R_0402]  200.88 44.11 270 top
RD12  0_0402_5%  [R0402_0OHM]  202.6 43.21 180 top
RD14  1K_0402_5%  [R_0402]  138.44 46.13 0 top
RD15  1K_0402_1%  [R_0402]  140.81 44.6 0 top
RD16  1K_0402_1%  [R_0402]  144.42 43.82 270 top
RD17  2_0402_1%  [R_0402]  141.72 43.78 180 top
RD18  24.9_0402_1%  [R_0402]  139.07 44.68 180 top
RD19  100K_0402_5%  [R_0402]  122.49 77.22 180 top
RD20  0_0402_5%  [R_0402]  246.77 45.48 180 top
RD21  0_0402_5%  [R0402_0OHM]  244.23 45.26 180 top
RD22  0_0402_5%  [R0402_0OHM]  246.77 44.71 180 top
RD23  0_0402_5%  [R_0402]  244.23 44.5 180 top
RD24  0_0402_5%  [R_0402]  223.32 43.06 180 top
RD25  0_0402_5%  [R0402_0OHM]  222.41 42.3 0 top
RD26  0_0603_5%  [R0603_0OHM]  247.84 48.02 90 top
RD27  1K_0402_5%  [R_0402]  212.06 40.92 180 top
RD28  1K_0402_1%  [R_0402]  217.39 42.3 0 top
RD29  1K_0402_1%  [R_0402]  219.88 42.29 90 top
RD30  2_0402_1%  [R_0402]  219.12 42.29 90 top
RD31  24.9_0402_1%  [R_0402]  217.4 44.07 90 top
RE8  100K_0402_5%  [R_0402]  252.53 104.65 90 top
RE10  100K_0402_5%  [R_0402]  248.72 102.11 90 bottom
RE11  100K_0402_5%  [R_0402]  243.77 85.75 270 top
RE12  100K_0402_5%  [R_0402]  257.74 86.51 270 top
RE20  100K_0402_5%  [R_0402]  258.63 89.18 270 top
RE21  10K_0402_5%  [R_0402]  244.03 101.22 90 top
RE25  100K_0402_5%  [R_0402]  262.96 102.63 180 top
RE26  10_0402_5%  [R_0402]  263.91 104.34 180 top
RE30  0_0402_5%  [R0402_0OHM]  215.83 85.09 90 bottom
RE31  100K_0402_5%  [R_0402]  242.53 93.53 0 bottom
RE32  0_0402_5%  [R0402_0OHM]  245.17 90.99 90 bottom
RE33  1K_0402_5%  [R_0402]  243.44 94.3 180 bottom
RE35  10K_0402_5%  [R_0402]  255.05 104.63 90 top
RE37  2.2K_0402_5%  [R_0402]  260.41 89.18 270 top
RE43  2.2K_0402_5%  [R_0402]  259.52 89.18 270 top
RE48  10K_0402_5%  [R_0402]  73.06 57.38 270 bottom
RE51  10K_0402_5%  [R_0402]  73.05 54.8 90 bottom
RE55  100K_0402_5%  [R_0402]  242.51 87.13 180 top
RE56  10K_0402_5%  [R_0402]  251.65 86.64 270 bottom
RE57  1K_0402_5%  [R_0402]  242.13 85.61 180 top
RE58  100K_0402_5%  [R_0402]  242.51 86.37 180 top
RE59  0_0402_5%  [R0402_0OHM]  251.39 103.02 270 bottom
RE60  43_0402_5%  [R_0402]  251.65 104.65 90 top
RE63  100K_0402_5%  [R_0402]  247.02 107.52 180 top
RE64  300_0402_5%  [R_0402]  259.52 86.51 270 top
RE65  100_0402_1%  [R_0402]  247.02 106.75 180 top
RE67  10K_0402_5%  [R_0402]  251.72 77.04 180 top
RE68  100K_0402_5%  [R_0402]  254.31 74.04 90 top
RE69  8.2K_0402_5%  [R_0402]  253.3 83.97 270 top
RE70  2.2K_0402_5%  [R_0402]  249.99 81.56 270 top
RE71  10_0402_1%  [R_0402]  220.4 86 270 bottom
RE72  10K_0402_5%  [R_0402]  216.59 86 270 bottom
RE73  10K_0402_5%  [R_0402]  213.55 86 270 bottom
RE74  10K_0402_5%  [R_0402]  216.73 86.81 180 bottom
RE75  100K_0402_5%  [R_0402]  214.31 86 270 bottom
RE77  1.58K_0402_1%  [R_0402]  246.31 98.32 270 bottom
RE79  4.3K_0402_1%  [R_0402]  249.87 105.56 270 top
RE83  100K_0402_5%  [R_0402]  248.09 104.65 90 top
RE84  100K_0402_5%  [R_0402]  251.65 108.47 270 top
RE85  100K_0402_5%  [R_0402]  250.76 108.47 270 top
RE86  10K_0402_5%  [R_0402]  215.07 85.09 90 bottom
RE90  0_0402_5%  [R0402_0OHM]  249.99 83.21 270 top
RE91  100K_0402_5%  [R_0402]  249.49 102.11 90 bottom
RE92  100K_0402_5%  [R_0402]  249.36 89.18 270 bottom
RE93  100K_0201_5%  [R_0201]  247.11 108.28 180 top
RE94  75_0402_5%  [R_0402]  252.53 108.47 270 top
RE274  0_0402_5%  [R_0402]  255.96 88.26 90 top
RE275  0_0402_5%  [R0402_0OHM]  255.85 105.55 270 top
RE280  0_0402_5%  [R_0402]  255.96 79.25 90 top
RE288  100_0402_5%  [R_0402]  248.98 104.65 90 top
RE290  0_0402_5%  [R0402_0OHM]  243.77 91.53 270 top
RE292  0_0402_5%  [R_0402]  252.59 77.04 0 top
RE300  33K_0402_5%  [R_0402]  257.31 109.69 0 top
RE302  2.2K_0402_5%  [R_0402]  247.01 91.97 270 bottom
RE303  2.2K_0402_5%  [R_0402]  247.84 91.97 270 bottom
RE304  0_0402_5%  [R_0402]  270.37 93.55 0 top
RE306  0_0402_5%  [R_0402]  212.78 86 270 bottom
RE312  300_0402_5%  [R_0402]  256.85 86.51 270 top
RE313  10K_0402_5%  [R_0402]  255.96 86.51 270 top
RE314  100_0402_1%  [R_0402]  249.06 88.08 180 top
RE318  0_0402_5%  [R0402_0OHM]  251.65 86.51 270 top
RE340  10K_0402_5%  [R_0402]  254.31 89.18 270 top
RE342  10K_0402_5%  [R_0402]  260 92.78 0 top
RE343  240K_0402_5%  [R_0402]  246.06 84.83 90 top
RE349  43K_0402_1%  [R_0402]  260.92 91.84 180 top
RE350  33_0402_5%  [R_0402]  242.76 95.82 90 bottom
RE361  0_0402_5%  [R0402_0OHM]  265.79 97.23 0 top
RE362  100K_0402_5%  [R_0402]  244.53 85.75 270 top
RE365  100K_0402_5%  [R_0402]  244.91 104.65 90 top
RE505  100K_0402_5%  [R_0402]  245.3 85.75 270 top
RE507  100K_0402_5%  [R_0402]  244.67 93.58 180 top
RE508  100K_0402_5%  [R_0402]  244.41 91.91 270 bottom
RE526  10K_0402_5%  [R_0402]  244.03 104.65 90 top
RE532  4.7K_0402_5%  [R_0402]  264.93 99.51 180 top
RE536  0_0402_5%  [R_0402]  241.15 95.56 45 bottom
RE539  100_0402_5%  [R_0402]  264.93 97.99 180 top
RE541  100K_0402_5%  [R_0402]  240.9 121.1 0 top
RE543  1M_0402_5%  [R_0402]  243.14 123.7 90 top
RE546  10K_0402_5%  [R_0402]  247.45 120.39 90 top
RE547  100K_0402_5%  [R_0402]  264.02 96.21 0 top
RE548  0_0402_5%  [R0402_0OHM]  251.65 88.26 90 bottom
RE549  100K_0402_5%  [R_0402]  256.85 88.26 90 top
RE550  100K_0402_5%  [R_0402]  257.74 89.18 270 top
RE551  0_0402_5%  [R_0402]  241.87 119.4 270 top
RE552  0_0402_5%  [R0402_0OHM]  260.03 110.51 270 top
RE560  0_0402_5%  [R0402_0OHM]  223.03 85.1 180 bottom
RE561  100K_0402_5%  [R_0402]  260 91.08 0 top
RE565  0_0402_5%  [R0402_0OHM]  241.82 121.87 180 top
RE600  0_0402_5%  [R0402_0OHM]  254.24 104.7 180 top
RE601  0_0402_5%  [R0402_0OHM]  254.19 85.6 90 top
RE602  0_0402_5%  [R0402_0OHM]  261.3 88.26 90 top
RE603  0_0402_5%  [R0402_0OHM]  262.39 96.21 180 top
RE605  100K_0402_5%  [R_0402]  263 105.1 0 top
RE606  100K_0402_5%  [R_0402]  247.96 102.11 90 bottom
RE608  0_0402_5%  [R0402_0OHM]  252.41 85.6 90 top
RE703  0_0402_5%  [R0402_0OHM]  263.91 105.86 180 top
RE704  10K_0402_5%  [R_0402]  261.48 101.8 0 top
RE706  10K_0402_5%  [R_0402]  253.34 107.55 90 top
RE707  10K_0402_5%  [R_0402]  254.12 107.55 90 top
RE708  10K_0402_5%  [R_0402]  254.94 107.55 90 top
RE709  10K_0402_5%  [R_0402]  255.75 108.47 270 top
RE714  10K_0402_5%  [R_0402]  218.88 86 270 bottom
RE715  10K_0402_5%  [R_0402]  219.64 86 270 bottom
RE716  100K_0402_5%  [R_0402]  266.71 97.99 180 top
RE717  100K_0402_5%  [R_0402]  262.39 97.99 180 top
RE718  100K_0402_5%  [R_0402]  255.28 77.04 180 top
RE719  10K_0402_5%  [R_0402]  217.36 86 270 bottom
RE720  10K_0402_5%  [R_0402]  218.12 86 270 bottom
RE721  2.2K_0402_5%  [R_0402]  261.48 98.75 0 top
RE722  2.2K_0402_5%  [R_0402]  264.93 98.75 180 top
RE723  100K_0402_5%  [R_0402]  261.48 101.04 0 top
RE724  100K_0402_5%  [R_0402]  261.48 100.28 0 top
RE725  100K_0402_5%  [R_0402]  261.48 99.51 0 top
RE726  100K_0402_5%  [R_0402]  250.38 86.64 270 bottom
RE727  100K_0402_5%  [R_0402]  254.06 83.06 90 top
RE728  100K_0402_5%  [R_0402]  255.96 83.06 90 top
RE729  100K_0402_5%  [R_0402]  255.07 83.06 90 top
RE730  100K_0402_5%  [R_0402]  253.17 86.51 270 top
RE821  100K_0402_5%  [R_0402]  272.92 93.55 0 top
RE822  100K_0402_5%  [R_0402]  246.91 89.61 180 bottom
RE825  0_0402_5%  [R_0402]  255.95 112.23 0 top
RE826  10K_0402_5%  [R_0402]  258.55 112.23 180 top
RE828  100K_0402_5%  [R_0402]  253.69 114.27 0 top
RE829  10K_0402_5%  [R_0402]  252.48 110.5 0 top
RI13  10K_0402_5%  [R_0402]  291.73 72.46 180 top
RI14  22.1K_0402_1%  [R_0402]  296.55 70.3 180 top
RI27  0_0402_5%  [R_0402-NPM]  262.24 70.43 0 bottom
RI28  0_0402_5%  [R_0402-NPM]  262.24 71.19 0 bottom
RI29  0_0402_5%  [R_0402-NPM]  262.16 68.91 0 bottom
RI30  0_0402_5%  [R_0402-NPM]  262.16 69.67 0 bottom
RI47  0_0402_5%  [R_0402-NPM]  263.46 72.74 180 bottom
RI48  0_0402_5%  [R_0402-NPM]  263.46 71.98 180 bottom
RL1  10K_0402_5%  [R_0402]  270.06 112.77 90 top
RL2  10K_0402_5%  [R_0402]  267.95 112.77 90 top
RL3  0_0402_5%  [R0402_0OHM]  271.08 99.21 270 top
RL4  4.7K_0402_5%  [R_0402]  266.2 104.59 180 top
RL5  10K_0402_5%  [R_0402]  266.2 101.55 180 top
RL6  4.7K_0402_5%  [R_0402]  266.2 103.83 180 top
RL7  0_0402_5%  [R0402_0OHM]  265.29 102.31 0 top
RL8  0_0603_5%  [R0603_0OHM]  268.03 102.12 270 top
RL9  10K_0402_5%  [R_0402]  266.2 103.07 180 top
RL11  1M_0402_5%  [R_0402]  274.05 101.67 0 top
RL12  1K_0402_5%  [R_0402]  272.04 112.77 90 top
RL13  3.01K_0402_1%  [R_0402]  276.02 103.01 0 top
RL14  150_0402_5%  [R_0402]  286.14 114.44 180 top
RL15  75_0402_1%  [R_0402]  298.75 108.77 0 top
RL16  75_0402_1%  [R_0402]  298.75 107.5 0 top
RL17  75_0402_1%  [R_0402]  298.75 101.15 0 top
RL18  75_0402_1%  [R_0402]  298.75 99.88 0 top
RL19  150_0402_5%  [R_0402]  289.61 110.63 0 top
RL20  0_0402_5%  [R0402_0OHM]  285.22 113.68 0 top
RL29  1M_0402_5%  [R_0402]  285.22 112.91 0 top
RL34  0_0402_5%  [R0402_0OHM]  274.96 100.91 180 top
RL70  10K_0402_5%  [R_0402]  181.72 70.94 0 top
RL71  2.2_0603_5%  [R_0603]  278.25 103.45 0 top
RL72  2.2_0603_5%  [R_0603]  278.25 104.66 0 top
RL73  2.2_0603_5%  [R_0603]  278.25 105.86 0 top
RL74  2.2_0603_5%  [R_0603]  278.25 107.07 0 top
RL75  2.2_0603_5%  [R_0603]  278.25 108.28 0 top
RL76  2.2_0603_5%  [R_0603]  278.25 109.48 0 top
RL77  2.2_0603_5%  [R_0603]  278.25 110.69 0 top
RL78  2.2_0603_5%  [R_0603]  278.25 111.9 0 top
RN1  100K_0402_5%  [R_0402]  253.06 36.59 180 top
RN2  100K_0402_5%  [R_0402]  251.51 32.4 0 top
RN3  10K_0402_5%  [R_0402]  248.22 39.01 270 top
RN4  10K_0402_5%  [R_0402]  247.2 34.78 90 top
RN5  10K_0402_5%  [R_0402]  245.98 37.27 0 top
RN6  4.7K_0402_5%  [R_0402]  260.87 47.06 180 bottom
RN7  4.7K_0402_5%  [R_0402]  260.87 46.3 180 bottom
RN8  4.7K_0402_5%  [R_0402]  259.95 47.83 0 bottom
RN9  4.7K_0402_5%  [R_0402]  260.87 48.59 180 bottom
RN10  4.7K_0402_5%  [R_0402]  252.29 47.13 180 bottom
RN11  4.7K_0402_5%  [R_0402]  250.86 48.08 0 bottom
RN12  4.7K_0402_5%  [R_0402]  250.86 50.37 0 bottom
RN13  4.7K_0402_5%  [R_0402]  250.86 51.13 0 bottom
RN14  4.7K_0402_5%  [R_0402]  260.87 50.11 180 bottom
RN15  7.87K_0402_1%  [R_0402]  260.87 49.35 180 bottom
RN16  4.7K_0402_5%  [R_0402]  251.38 46.37 0 bottom
RN17  4.7K_0402_5%  [R_0402]  251.38 45.6 0 bottom
RN18  4.7K_0402_5%  [R_0402]  256.6 47.14 270 top
RN19  4.7K_0402_5%  [R_0402]  255.84 46.23 90 top
RN20  4.7K_0402_5%  [R_0402]  250.86 49.6 0 bottom
RN21  4.7K_0402_5%  [R_0402]  251.77 48.84 180 bottom
RN37  10K_0402_5%  [R_0402]  273.54 23.22 90 top
RN77  0_0402_5%  [R0402_0OHM]  272.11 28.27 90 top
RN78  0_0402_5%  [R0402_0OHM]  271.35 28.27 90 top
RN81  0_0402_5%  [R0402_0OHM]  274.78 28.27 90 top
RN82  0_0402_5%  [R0402_0OHM]  275.54 28.27 90 top
RN99  0_0402_5%  [R0402_0OHM]  270.19 24.64 90 top
RN100  0_0402_5%  [R_0402]  275.45 24.18 180 top
RN101  0_0402_5%  [R_0402]  261.78 79.53 270 top
RN125  0_0402_5%  [R0402_0OHM]  278.97 28.27 90 top
RN126  0_0402_5%  [R0402_0OHM]  278.2 28.27 90 top
RN127  0_0402_5%  [R0402_0OHM]  282.4 28.27 90 top
RN128  0_0402_5%  [R0402_0OHM]  281.63 28.27 90 top
RN129  0_0402_5%  [R0402_0OHM]  275.45 24.94 180 top
RN131  0.01_0805_1%  [R_0805]  262.02 33.09 180 top
RN226  4.7K_0402_5%  [R_0402]  259.95 51.64 0 bottom
RN227  0_0402_5%  [R0402_0OHM]  260.87 50.87 180 bottom
RR3  10K_0402_5%  [R_0402]  290.79 28.17 270 top
RR4  6.2K_0402_1%  [R_0402]  287.28 21.03 180 top
RR5  0_0402_5%  [R0402_0OHM]  294.95 21.36 270 top
RR6  0_0402_5%  [R0402_0OHM]  294.84 22.82 0 top
RR7  0_0402_5%  [R0402_0OHM]  294.84 23.58 0 top
RR8  0_0402_5%  [R0402_0OHM]  294.84 24.34 0 top
RR9  0_0402_5%  [R0402_0OHM]  294.88 18.74 0 top
RR10  0_0402_5%  [R0402_0OHM]  294.88 19.5 0 top
RR19  10K_0402_5%  [R_0402]  288.43 26.74 180 top
RR20  0_0603_5%  [R0603_0OHM]  289.65 29.55 270 top
RT50  3.3K_0402_5%  [R_0402]  36.94 88.85 0 bottom
RT51  3.3K_0402_5%  [R_0402]  51.06 90.37 180 bottom
RT52  3.3K_0402_5%  [R_0402]  51.06 88.85 180 bottom
RT53  3.3K_0402_5%  [R_0402]  51.06 87.58 180 bottom
RT54  0_0402_5%  [R0402_0OHM]  36.94 87.58 0 bottom
RT55  0_0402_5%  [R0402_0OHM]  36.94 86.31 0 bottom
RT56  0_0402_5%  [R0402_0OHM]  51.06 89.61 180 bottom
RT57  0_0402_5%  [R0402_0OHM]  51.06 91.13 180 bottom
RT58  0_0402_5%  [R0402_0OHM]  59.24 94.49 90 top
RT59  0_0402_5%  [R0402_0OHM]  62.54 97.05 270 top
RT60  0_0402_5%  [R0402_0OHM]  61.72 99.09 90 bottom
RT63  0_0402_5%  [R0402_0OHM]  54.82 103.48 180 bottom
RT64  0_0402_5%  [R_0402]  62.49 100 270 bottom
RT65  0_0402_5%  [R_0402]  63.25 100 270 bottom
RT66  3.3K_0402_5%  [R_0402]  62.54 95.4 270 top
RT67  3.3K_0402_5%  [R_0402]  59.24 96.14 90 top
RT68  10K_0402_5%  [R_0402]  60.96 100 270 bottom
RT69  0_0402_5%  [R0402_0OHM]  55.37 100.57 270 top
RT70  0_0402_5%  [R0402_0OHM]  54.82 101.45 180 bottom
RT71  1M_0402_5%  [R_0402]  63.38 102.94 180 top
RT72  0_0402_5%  [R_0402]  66.4 107.26 0 bottom
